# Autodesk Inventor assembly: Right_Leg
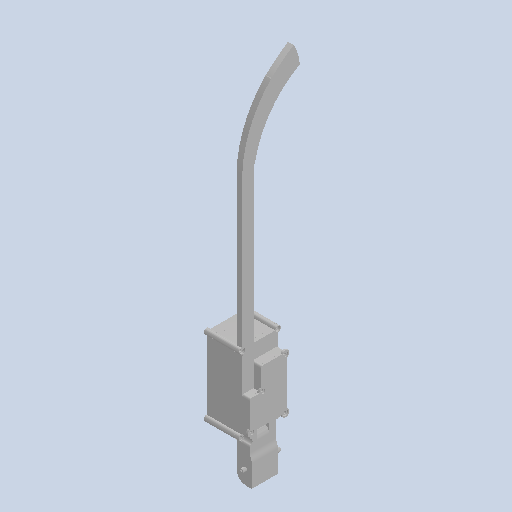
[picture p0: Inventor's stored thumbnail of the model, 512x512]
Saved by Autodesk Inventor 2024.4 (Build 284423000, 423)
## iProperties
Created: 2025-05
Part Number: Right_Leg
Document SubType Name: Assembly
Designer: AdminForWorker
Title: Right_Leg
Author: AdminForWorker
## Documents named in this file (4)
- c:\worker\convert-fusion-r02-cosv3\tmp\job-1\2\temp\files\be827049-a7f2-47ea-a815-8d9efd6bfce9\Right_Leg.iam
- c:\worker\convert-fusion-r02-cosv3\tmp\job-1\2\temp\files\be827049-a7f2-47ea-a815-8d9efd6bfce9\Battery_LCD_Holder.ipt
- c:\worker\convert-fusion-r02-cosv3\tmp\job-1\2\temp\files\be827049-a7f2-47ea-a815-8d9efd6bfce9\Bat_LCD_Top.ipt
- c:\worker\convert-fusion-r02-cosv3\tmp\job-1\2\temp\files\be827049-a7f2-47ea-a815-8d9efd6bfce9\Charge_Modules.ipt
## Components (3 placed, 3 different names)
1. Battery_LCD_Holder:1
2. Bat_LCD_Top:1
3. Charge_Modules:1
